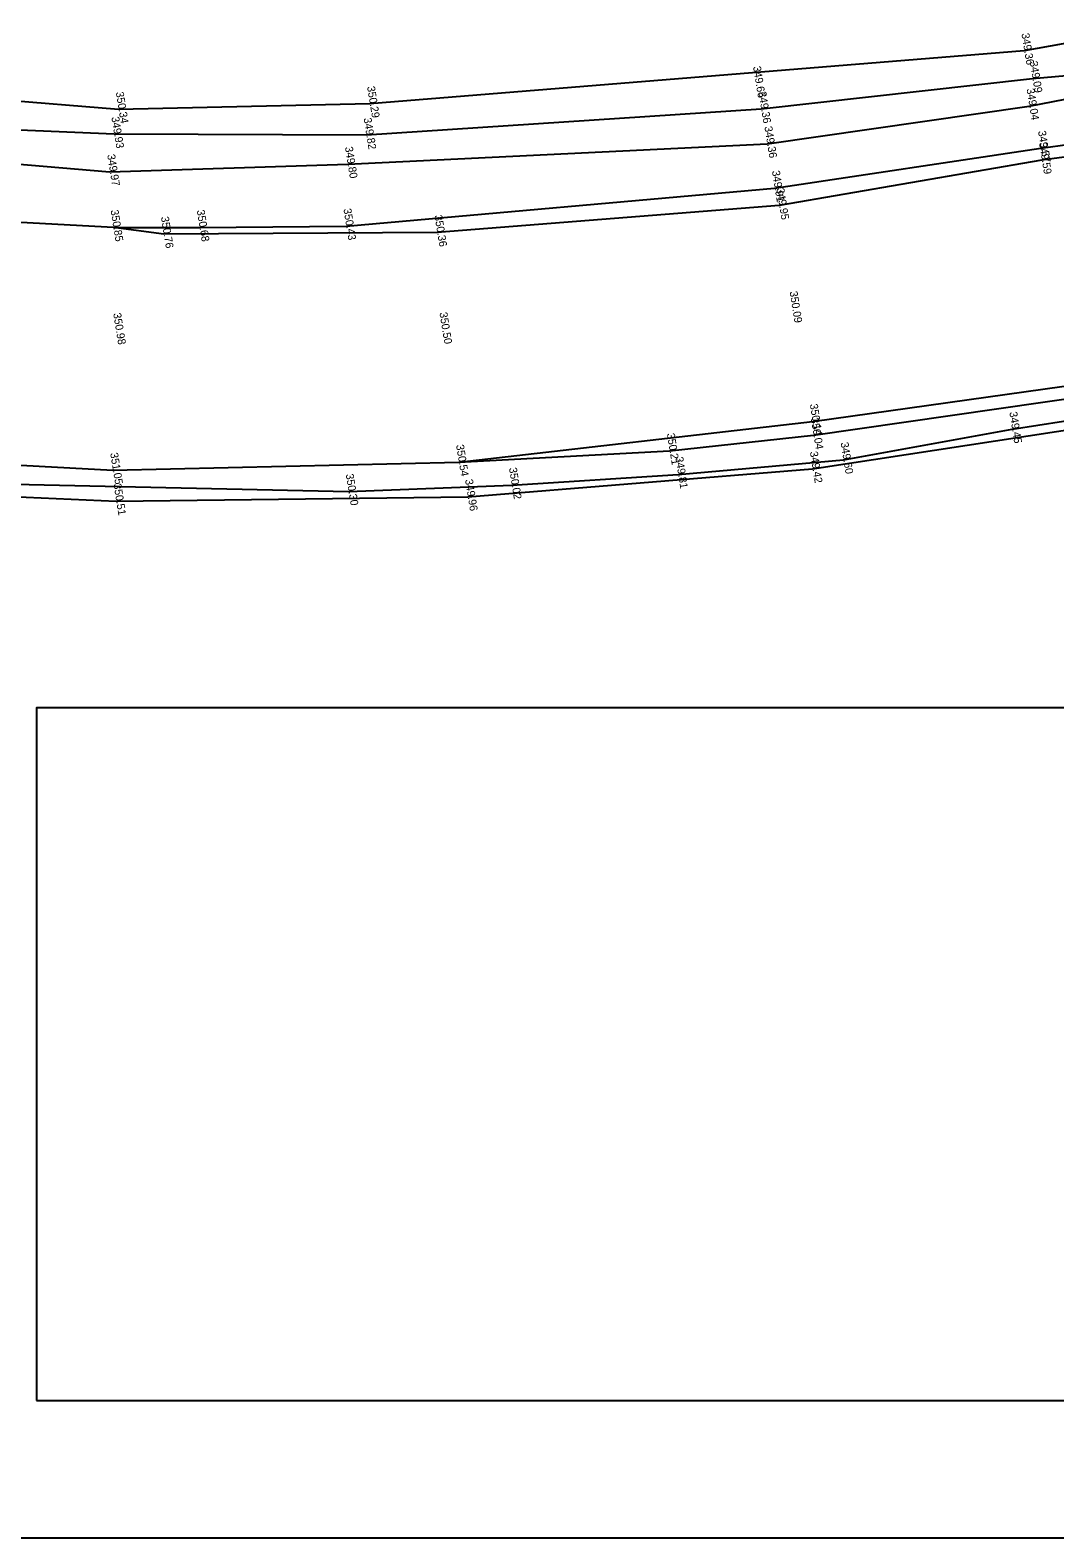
# Model space of a CAD drawing. Extents: x -600096 to -597522, y -1151695 to -1149849.
# Drawn here: x -599566.69 to -599542.24, y -1151620.38 to -1151584.41 of the extents above; entities that cross this region are included whole.
import ezdxf

# ---------------------------------------------------------------- set-up
doc = ezdxf.new("R2010")
doc.units = 0
for name, color, linetype in [('ADJ_severka', 7, 'Continuous'), ('Hrana komunikace', 7, 'Continuous'), ('MPPV_Dno_prikopu', 7, 'Continuous'), ('MPPV_komunikace', 7, 'Continuous'), ('MPPV_svah', 7, 'Continuous'), ('Ram03', 7, 'Continuous'), ('Svodidla', 7, 'Continuous'), ('Vrstva 12', 7, 'Continuous')]:
    doc.layers.add(name, color=color, linetype=linetype)

msp = doc.modelspace()

# ---------------------------------------------------------------- linework, layer by layer
at = {"layer": 'ADJ_severka'}
msp.add_lwpolyline([(-599566.541, -1151617.107), (-599521.98, -1151617.107), (-599521.98, -1151600.58), (-599566.541, -1151600.58)], close=True, dxfattribs=at)
at = {"layer": 'Hrana komunikace'}
for p, q in [((-599542.577, -1151587.23), (-599539.872, -1151586.856)), ((-599548.927, -1151588.18), (-599542.577, -1151587.23)), ((-599559.153, -1151589.084), (-599548.927, -1151588.18)), ((-599564.708, -1151589.117), (-599562.651, -1151589.12)), ((-599562.651, -1151589.12), (-599559.153, -1151589.084)), ((-599547.999, -1151594.077), (-599541.416, -1151593.13)), ((-599551.434, -1151594.447), (-599547.999, -1151594.077)), ((-599556.464, -1151594.719), (-599551.434, -1151594.447))]:
    msp.add_line(p, q, dxfattribs=at)
at = {"layer": 'MPPV_Dno_prikopu'}
for p, q in [((-599539.977, -1151585.323), (-599542.773, -1151585.57)), ((-599542.773, -1151585.57), (-599549.25, -1151586.297)), ((-599542.851, -1151586.221), (-599539.933, -1151585.66)), ((-599549.25, -1151586.297), (-599558.67, -1151586.92)), ((-599549.106, -1151587.125), (-599542.851, -1151586.221)), ((-599564.69, -1151586.896), (-599571.676, -1151586.601)), ((-599571.867, -1151587.178), (-599564.789, -1151587.793)), ((-599558.67, -1151586.92), (-599564.69, -1151586.896)), ((-599559.116, -1151587.61), (-599549.106, -1151587.125)), ((-599564.789, -1151587.793), (-599559.116, -1151587.61))]:
    msp.add_line(p, q, dxfattribs=at)
at = {"layer": 'MPPV_komunikace'}
for p, q in [((-599539.744, -1151587.149), (-599542.552, -1151587.51)), ((-599542.552, -1151587.51), (-599548.819, -1151588.598)), ((-599548.819, -1151588.598), (-599556.98, -1151589.242)), ((-599564.708, -1151589.117), (-599572.319, -1151588.71)), ((-599563.507, -1151589.278), (-599564.708, -1151589.117)), ((-599556.98, -1151589.242), (-599563.507, -1151589.278)), ((-599548.022, -1151593.747), (-599541.564, -1151592.84)), ((-599556.464, -1151594.719), (-599548.022, -1151593.747)), ((-599572.66, -1151594.467), (-599564.718, -1151594.912)), ((-599564.718, -1151594.912), (-599556.464, -1151594.719))]:
    msp.add_line(p, q, dxfattribs=at)
at = {"layer": 'MPPV_svah'}
for p, q in [((-599540.225, -1151584.411), (-599542.971, -1151584.903)), ((-599542.971, -1151584.903), (-599558.589, -1151586.168)), ((-599564.583, -1151586.301), (-599571.447, -1151585.754)), ((-599558.589, -1151586.168), (-599564.583, -1151586.301)), ((-599548.022, -1151594.881), (-599541.399, -1151593.867)), ((-599556.25, -1151595.546), (-599548.022, -1151594.881)), ((-599572.811, -1151595.291), (-599564.64, -1151595.649)), ((-599564.64, -1151595.649), (-599556.25, -1151595.546))]:
    msp.add_line(p, q, dxfattribs=at)
at = {"layer": 'Ram03'}
msp.add_line((-600095.903, -1151620.382), (-599518.403, -1151620.382), dxfattribs=at)
msp.add_line((-600095.903, -1151620.382), (-599518.403, -1151620.382), dxfattribs=at)
at = {"layer": 'Svodidla'}
for p, q in [((-599543.262, -1151593.934), (-599539.388, -1151593.331)), ((-599547.287, -1151594.662), (-599543.262, -1151593.934)), ((-599551.232, -1151595.012), (-599547.287, -1151594.662)), ((-599555.202, -1151595.266), (-599551.232, -1151595.012)), ((-599567.086, -1151595.242), (-599559.097, -1151595.416)), ((-599559.097, -1151595.416), (-599555.202, -1151595.266))]:
    msp.add_line(p, q, dxfattribs=at)

# ---------------------------------------------------------------- texts
at = {"layer": 'Vrstva 12'}
for s, p in [('349.36 ', (-599543.037, -1151584.495)), ('349.66 ', (-599549.443, -1151585.282)), ('349.09 ', (-599542.839, -1151585.162)), ('350.29 ', (-599558.654, -1151585.76)), ('350.34 ', (-599564.649, -1151585.893)), ('349.36 ', (-599549.315, -1151585.889)), ('349.04 ', (-599542.916, -1151585.813)), ('349.93 ', (-599564.756, -1151586.488)), ('349.82 ', (-599558.736, -1151586.513)), ('349.36 ', (-599549.172, -1151586.717)), ('349.57 ', (-599542.643, -1151586.822)), ('349.80 ', (-599559.182, -1151587.202)), ('349.59 ', (-599542.618, -1151587.102)), ('349.97 ', (-599564.855, -1151587.385)), ('349.91 ', (-599548.992, -1151587.772)), ('349.95 ', (-599548.885, -1151588.19)), ('350.85 ', (-599564.774, -1151588.709)), ('350.76 ', (-599563.573, -1151588.87)), ('350.68 ', (-599562.717, -1151588.712)), ('350.43 ', (-599559.218, -1151588.677)), ('350.36 ', (-599557.046, -1151588.834)), ('350.09 ', (-599548.57, -1151590.651)), ('350.98 ', (-599564.712, -1151591.17)), ('350.50 ', (-599556.926, -1151591.154)), ('350.14 ', (-599548.087, -1151593.339)), ('350.04 ', (-599548.064, -1151593.669)), ('349.45 ', (-599543.327, -1151593.526)), ('350.21 ', (-599551.499, -1151594.039)), ('350.54 ', (-599556.53, -1151594.311)), ('349.60 ', (-599547.353, -1151594.254)), ('351.05 ', (-599564.784, -1151594.504)), ('349.81 ', (-599551.297, -1151594.604)), ('349.42 ', (-599548.087, -1151594.473)), ('350.30 ', (-599559.163, -1151595.008)), ('349.96 ', (-599556.316, -1151595.138)), ('350.02 ', (-599555.267, -1151594.858)), ('350.51 ', (-599564.706, -1151595.241))]:
    msp.add_text(s, height=0.1875, rotation=279.1328, dxfattribs=at).set_placement(p)

doc.saveas('drawing.dxf')
